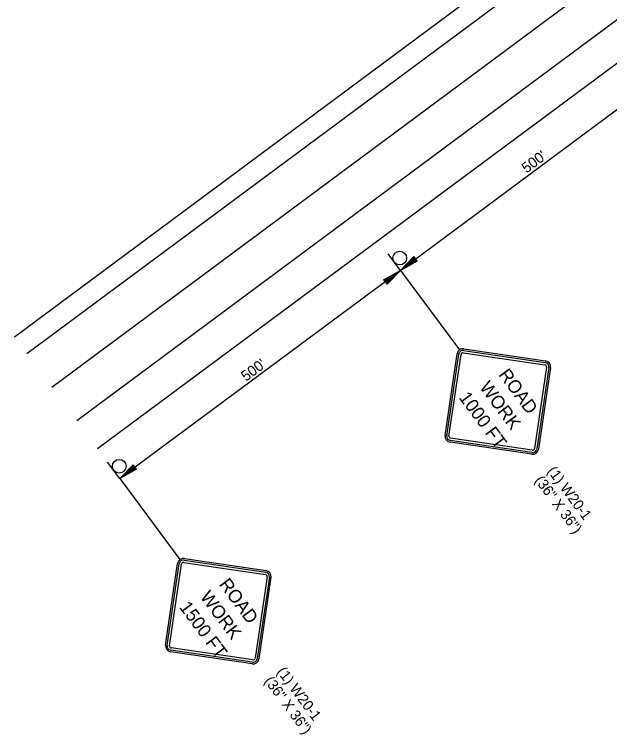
# Model space of a CAD drawing. Extents: x -238 to 1487, y -1123 to 446.
# Drawn here: x 32.9 to 373.5, y -1122.8 to -710.5 of the extents above; entities that cross this region are included whole.
import ezdxf

# ---------------------------------------------------------------- set-up
doc = ezdxf.new("R2010")
doc.units = 0
for name, color, linetype in [('P_TC_Signs_Temporary', 7, 'Continuous'), ('R_Border Prem', 7, 'Continuous'), ('R_Draft', 7, 'Continuous'), ('STAMP', 7, 'Continuous')]:
    doc.layers.add(name, color=color, linetype=linetype)

msp = doc.modelspace()

# ---------------------------------------------------------------- linework, layer by layer
at = {"layer": 'P_TC_Signs_Temporary'}
for p, q in [((289.98, -902.9), (336.73, -909.8)), ((290.12, -901.97), (336.86, -908.88)), ((279.38, -951.56), (286.29, -904.82)), ((280.31, -951.7), (287.22, -904.95)), ((281.61, -951.89), (288.51, -905.14)), ((289.79, -904.2), (336.53, -911.1)), ((337.48, -912.38), (330.58, -959.12)), ((338.78, -912.57), (331.88, -959.31)), ((339.71, -912.71), (332.8, -959.45)), ((328.97, -962.3), (282.23, -955.39)), ((329.11, -961.37), (282.37, -954.46)), ((329.3, -960.07), (282.56, -953.16)), ((130.15, -1022.01), (176.89, -1028.92)), ((119.41, -1071.6), (126.32, -1024.86)), ((120.34, -1071.73), (127.24, -1024.99)), ((121.64, -1071.93), (128.54, -1025.18)), ((129.82, -1024.24), (176.56, -1031.14)), ((130.01, -1022.94), (176.75, -1029.84)), ((177.51, -1032.42), (170.6, -1079.16)), ((178.81, -1032.61), (171.9, -1079.35)), ((179.74, -1032.75), (172.83, -1079.49)), ((169, -1082.34), (122.25, -1075.43)), ((169.13, -1081.41), (122.39, -1074.5)), ((169.33, -1080.11), (122.58, -1073.2))]:
    msp.add_line(p, q, dxfattribs=at)
for centre, radius, start, end in [((289.63, -905.31), 3.38, 81.5953, 171.5953), ((289.63, -905.31), 2.44, 81.5953, 171.5953), ((289.63, -905.31), 1.12, 81.5953, 171.5953), ((336.37, -912.22), 1.13, 351.5953, 81.5953), ((336.37, -912.22), 2.44, 351.5953, 81.5953), ((336.37, -912.22), 3.37, 351.5953, 81.5953), ((282.72, -952.05), 3.37, 171.5953, 261.5953), ((282.72, -952.05), 2.44, 171.5953, 261.5953), ((282.72, -952.05), 1.13, 171.5953, 261.5953), ((329.46, -958.96), 3.38, 261.5953, 351.5953), ((329.46, -958.96), 2.44, 261.5953, 351.5953), ((329.46, -958.96), 1.12, 261.5953, 351.5953), ((129.65, -1025.35), 3.38, 81.5953, 171.5953), ((129.65, -1025.35), 2.44, 81.5953, 171.5953), ((129.65, -1025.35), 1.12, 81.5953, 171.5953), ((176.4, -1032.25), 2.44, 351.5953, 81.5953), ((176.4, -1032.25), 3.38, 351.5953, 81.5953), ((176.4, -1032.25), 1.13, 351.5953, 81.5953), ((122.75, -1072.09), 3.38, 171.5953, 261.5953), ((122.75, -1072.09), 2.44, 171.5953, 261.5953), ((122.75, -1072.09), 1.13, 171.5953, 261.5953), ((169.49, -1079), 3.38, 261.5953, 351.5953), ((169.49, -1079), 2.44, 261.5953, 351.5953), ((169.49, -1079), 1.12, 261.5953, 351.5953)]:
    msp.add_arc(centre, radius, start, end, dxfattribs=at)
at = {"layer": 'R_Draft'}
for p, q in [((54.3, -923.87), (605.38, -514.67)), ((32.89, -895.04), (504.89, -544.56)), ((40.03, -904.65), (512.02, -554.17)), ((68.57, -943.09), (540.56, -592.61)), ((80.46, -959.1), (552.46, -608.63)), ((414.36, -737.81), (253.79, -857.04)), ((261.43, -849.12), (253.79, -857.04)), ((261.59, -849.34), (255.23, -855.94)), ((263.41, -851.71), (261.43, -849.12)), ((263.41, -851.71), (253.79, -857.04)), ((263.25, -851.5), (255.23, -855.94)), ((261.76, -849.56), (256.71, -854.8)), ((263.08, -851.28), (256.71, -854.8)), ((261.93, -849.78), (258.15, -853.69)), ((262.91, -851.06), (258.15, -853.69)), ((262.1, -850), (259.62, -852.57)), ((262.74, -850.84), (259.62, -852.57)), ((262.26, -850.21), (261.06, -851.46)), ((262.58, -850.62), (261.06, -851.46)), ((253.79, -857.04), (93.22, -976.28)), ((244.17, -862.38), (253.79, -857.04)), ((246.15, -864.97), (253.79, -857.04)), ((253.79, -857.04), (287.62, -902.6)), ((244.33, -862.59), (252.35, -858.15)), ((244.5, -862.81), (250.87, -859.29)), ((244.67, -863.03), (249.43, -860.4)), ((244.84, -863.25), (247.96, -861.52)), ((245.48, -864.09), (247.96, -861.52)), ((245.65, -864.32), (249.43, -860.4)), ((245.82, -864.53), (250.87, -859.29)), ((245.99, -864.75), (252.35, -858.15)), ((244.17, -862.38), (246.15, -864.97)), ((245, -863.47), (246.53, -862.62)), ((245.31, -863.87), (246.53, -862.62)), ((100.85, -968.35), (93.22, -976.28)), ((101.02, -968.57), (94.66, -975.17)), ((101.19, -968.79), (96.14, -974.03)), ((102.84, -970.94), (100.85, -968.35)), ((102.84, -970.94), (93.22, -976.28)), ((102.67, -970.73), (94.66, -975.17)), ((102.5, -970.51), (96.14, -974.03)), ((101.35, -969.01), (97.58, -972.92)), ((102.34, -970.29), (97.58, -972.92)), ((101.52, -969.23), (99.04, -971.8)), ((102.17, -970.07), (99.04, -971.8)), ((101.69, -969.45), (100.48, -970.69)), ((102, -969.85), (100.48, -970.69)), ((93.22, -976.28), (127.64, -1022.64))]:
    msp.add_line(p, q, dxfattribs=at)
at = {"layer": 'STAMP'}
for p, q in [((253.79, -857.04), (246.79, -847.6)), ((93.22, -976.28), (86.22, -966.83))]:
    msp.add_line(p, q, dxfattribs=at)
for centre in [(253.44, -849.99), (92.86, -969.22)]:
    msp.add_circle(centre, 3.92, dxfattribs=at)

# ---------------------------------------------------------------- texts
at = {"layer": 'P_TC_Signs_Temporary'}
for s, p in [(' ROAD ', (307.99, -914.58)), ('WORK', (298.74, -923.98)), ('1000 FT', (286.92, -929.89)), (' ROAD ', (148.01, -1034.62)), ('WORK', (138.77, -1044.02)), ('1500 FT', (126.94, -1049.93))]:
    msp.add_text(s, height=7.5, rotation=306.5953, dxfattribs=at).set_placement(p)
at = {"layer": 'R_Border Prem'}
for s, rotation, p in [("500'", 36.5953, (325.98, -801.66)), ("500'", 36.5953, (165.41, -920.9)), ('(1) W20-1', 306.5953, (337.61, -971.94)), ('(36" X 36")', 306.5953, (330.38, -977.31)), ('(1) W20-1', 306.5953, (182.87, -1086.8)), ('(36" X 36")', 306.5953, (175.64, -1092.16))]:
    msp.add_text(s, height=6, rotation=rotation, dxfattribs=at).set_placement(p)

doc.saveas('drawing.dxf')
